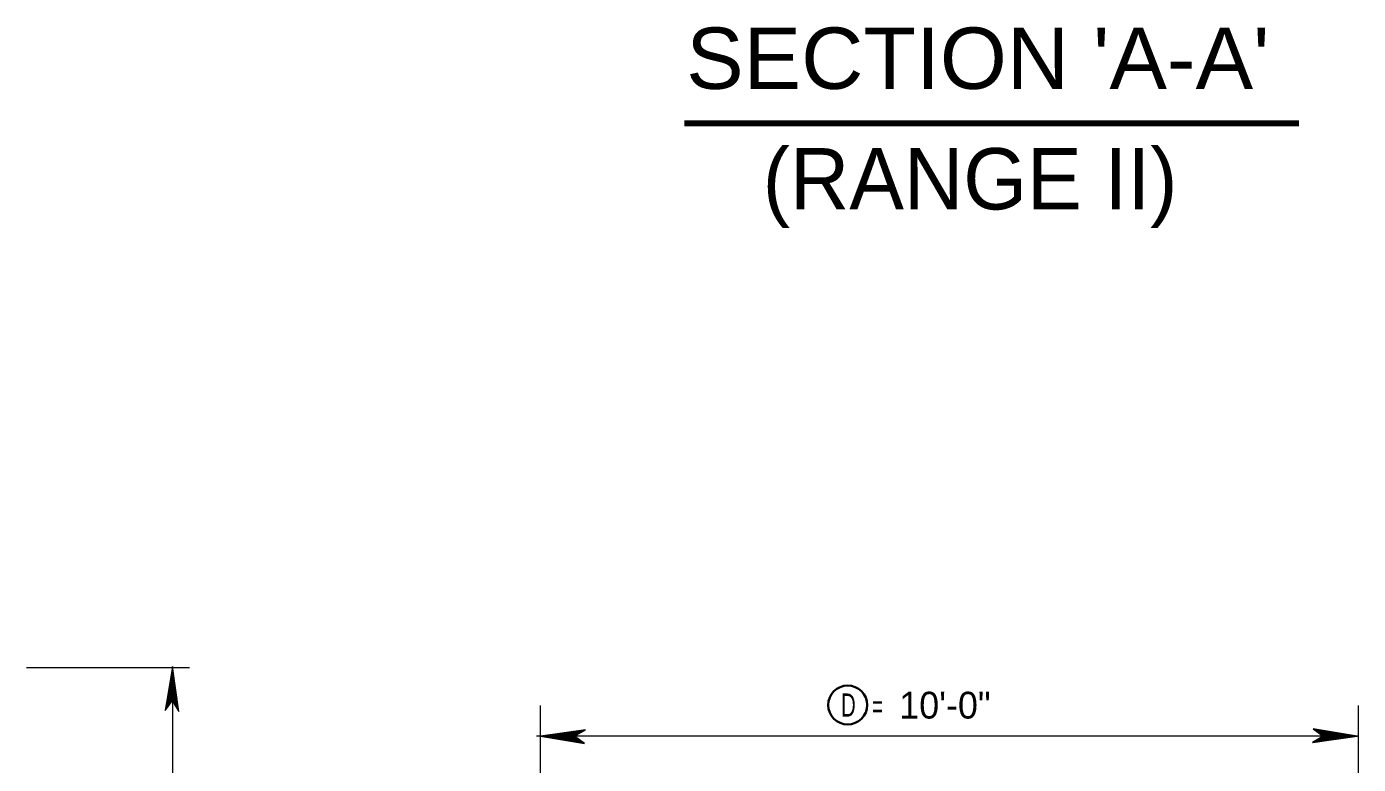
# Model space of a CAD drawing. Extents: x 144 to 252, y 360 to 425.
# Drawn here: x 182.53 to 198.81, y 378.68 to 387.71 of the extents above; entities that cross this region are included whole.
import ezdxf
from ezdxf.enums import TextEntityAlignment as Align

# ---------------------------------------------------------------- set-up
doc = ezdxf.new("R2010")
doc.units = 0
doc.header["$LTSCALE"] = 0.13
for name, color, linetype, lineweight in [('1', 7, 'Continuous', 40), ('14', 7, 'Continuous', 13), ('16', 7, 'Continuous', 13), ('3', 7, 'Continuous', 13)]:
    doc.layers.add(name, color=color, linetype=linetype, lineweight=lineweight)

msp = doc.modelspace()

# ---------------------------------------------------------------- linework, layer by layer
at = {"layer": '1', "lineweight": 13}
for p, q in [((184.5221, 379.866), (182.5307, 379.866)), ((184.3167, 377.2068), (184.3167, 379.8775))]:
    msp.add_line(p, q, dxfattribs=at)
at = {"layer": '1', "lineweight": 35}
msp.add_circle((192.5684, 379.409), 0.238, dxfattribs=at)
at = {"layer": '14', "lineweight": 106}
msp.add_line((190.5739, 386.5247), (198.0812, 386.5247), dxfattribs=at)
at = {"layer": '3'}
for p, q in [((184.3126, 379.8803), (184.2233, 379.3427)), ((184.3119, 379.8659), (184.2257, 379.3459)), ((184.3119, 379.8551), (184.228, 379.3492)), ((184.3119, 379.8407), (184.2312, 379.3534)), ((184.3119, 379.8279), (184.2338, 379.3572)), ((184.3119, 379.8166), (184.2362, 379.3605)), ((184.3868, 379.3376), (184.3119, 379.8659)), ((184.3848, 379.3411), (184.3119, 379.8551)), ((184.3822, 379.3457), (184.3119, 379.8407)), ((184.3798, 379.3497), (184.3119, 379.8279)), ((184.3798, 379.3497), (184.3119, 379.8279)), ((184.3776, 379.3534), (184.3119, 379.8166)), ((184.3126, 379.4649), (184.3126, 379.8803)), ((184.3903, 379.3316), (184.3126, 379.8803)), ((184.3119, 379.8022), (184.2394, 379.3648)), ((184.3119, 379.7894), (184.2422, 379.3685)), ((184.3119, 379.7757), (184.2451, 379.3726)), ((184.3119, 379.7618), (184.2481, 379.3767)), ((184.3119, 379.7486), (184.2509, 379.3806)), ((184.3119, 379.7347), (184.2539, 379.3847)), ((184.3119, 379.7221), (184.2566, 379.3884)), ((184.3119, 379.7107), (184.2591, 379.3918)), ((184.3119, 379.695), (184.2624, 379.3964)), ((184.3119, 379.6812), (184.2654, 379.4005)), ((184.3114, 379.6632), (184.2685, 379.4047)), ((184.3481, 379.404), (184.3114, 379.6632)), ((184.3749, 379.358), (184.3119, 379.8022)), ((184.3725, 379.3621), (184.3119, 379.7894)), ((184.37, 379.3665), (184.3119, 379.7757)), ((184.3674, 379.3709), (184.3119, 379.7618)), ((184.3649, 379.3752), (184.3119, 379.7486)), ((184.3622, 379.3797), (184.3119, 379.7347)), ((184.36, 379.3837), (184.3119, 379.7221)), ((184.3577, 379.3874), (184.3119, 379.7107)), ((184.3549, 379.3924), (184.3119, 379.695)), ((184.3522, 379.3968), (184.3119, 379.6812)), ((184.35, 379.4008), (184.313, 379.6616)), ((184.3114, 379.6492), (184.2715, 379.4089)), ((184.3114, 379.6361), (184.2743, 379.4127)), ((184.3119, 379.627), (184.2771, 379.4165)), ((184.3119, 379.615), (184.2797, 379.4201)), ((184.3119, 379.6012), (184.2827, 379.4242)), ((184.3119, 379.5855), (184.2859, 379.4288)), ((184.3119, 379.5729), (184.2887, 379.4325)), ((184.3119, 379.5597), (184.2915, 379.4364)), ((184.3119, 379.5477), (184.2942, 379.44)), ((184.3119, 379.5332), (184.2972, 379.4443)), ((184.3119, 379.5193), (184.3002, 379.4484)), ((184.3119, 379.5067), (184.3029, 379.4521)), ((184.3119, 379.4934), (184.3057, 379.456)), ((184.3455, 379.4084), (184.3114, 379.6492)), ((184.343, 379.4127), (184.3114, 379.6361)), ((184.3422, 379.4142), (184.3119, 379.627)), ((184.3399, 379.4181), (184.3119, 379.615)), ((184.3372, 379.4225), (184.3119, 379.6012)), ((184.3344, 379.4275), (184.3119, 379.5855)), ((184.332, 379.4316), (184.3119, 379.5729)), ((184.3295, 379.4358), (184.3119, 379.5597)), ((184.3272, 379.4397), (184.3119, 379.5477)), ((184.3246, 379.4443), (184.3119, 379.5332)), ((184.322, 379.4487), (184.3119, 379.5193)), ((184.3197, 379.4528), (184.3119, 379.5067)), ((184.2233, 379.3427), (184.3124, 379.4652)), ((184.3119, 379.482), (184.3082, 379.4594)), ((184.3119, 379.4718), (184.3104, 379.4624)), ((184.315, 379.4607), (184.3119, 379.482)), ((184.3124, 379.4652), (184.3903, 379.3316)), ((184.3166, 379.4581), (184.313, 379.4832)), ((188.8108, 376.1394), (188.8108, 379.4017)), ((198.8108, 375.9887), (198.8108, 379.4017)), ((188.8108, 379.0267), (188.7653, 379.0267)), ((189.3618, 379.106), (188.813, 379.0283)), ((188.813, 379.0283), (189.3507, 378.939)), ((189.2284, 379.0283), (188.813, 379.0283)), ((194.8025, 379.0267), (188.8198, 379.0267)), ((189.3558, 379.1025), (188.8274, 379.0276)), ((188.8274, 379.0276), (189.3474, 378.9413)), ((189.3522, 379.1005), (188.8382, 379.0276)), ((188.8382, 379.0276), (189.3442, 378.9437)), ((189.3477, 379.0978), (188.8527, 379.0276)), ((188.8527, 379.0276), (189.3399, 378.9468)), ((189.3436, 379.0954), (188.8654, 379.0276)), ((189.3436, 379.0954), (188.8654, 379.0276)), ((188.8654, 379.0276), (189.3362, 378.9495)), ((189.3399, 379.0933), (188.8767, 379.0276)), ((188.8767, 379.0276), (189.3328, 378.9519)), ((189.3353, 379.0906), (188.8912, 379.0276)), ((188.8912, 379.0276), (189.3286, 378.9551)), ((189.3312, 379.0882), (188.9039, 379.0276)), ((188.9039, 379.0276), (189.3248, 378.9578)), ((189.3268, 379.0857), (188.9177, 379.0276)), ((188.9177, 379.0276), (189.3208, 378.9607)), ((189.3224, 379.0831), (188.9315, 379.0276)), ((188.9315, 379.0276), (189.3167, 378.9638)), ((189.3182, 379.0806), (188.9447, 379.0276)), ((188.9447, 379.0276), (189.3127, 378.9666)), ((189.3137, 379.0779), (188.9587, 379.0276)), ((188.9587, 379.0276), (189.3087, 378.9696)), ((189.3097, 379.0757), (188.9712, 379.0276)), ((188.9712, 379.0276), (189.3049, 378.9722)), ((189.3059, 379.0734), (188.9827, 379.0276)), ((188.9827, 379.0276), (189.3015, 378.9747)), ((189.3009, 379.0706), (188.9983, 379.0276)), ((188.9983, 379.0276), (189.2969, 378.9781)), ((189.2965, 379.0679), (189.0122, 379.0276)), ((189.0122, 379.0276), (189.2928, 378.9811)), ((189.2893, 379.0637), (189.0302, 379.0271)), ((189.0302, 379.0271), (189.2886, 378.9842)), ((189.2925, 379.0657), (189.0317, 379.0287)), ((189.2849, 379.0612), (189.0441, 379.0271)), ((189.0441, 379.0271), (189.2844, 378.9872)), ((189.2807, 379.0587), (189.0572, 379.0271)), ((189.0572, 379.0271), (189.2806, 378.99)), ((189.2792, 379.0578), (189.0663, 379.0276)), ((189.0663, 379.0276), (189.2768, 378.9928)), ((189.2752, 379.0556), (189.0783, 379.0276)), ((189.0783, 379.0276), (189.2732, 378.9953)), ((189.2708, 379.0529), (189.0922, 379.0276)), ((189.0922, 379.0276), (189.2692, 378.9983)), ((189.2658, 379.0501), (189.1078, 379.0276)), ((189.1078, 379.0276), (189.2645, 379.0016)), ((189.2618, 379.0477), (189.1204, 379.0276)), ((189.1204, 379.0276), (189.2608, 379.0043)), ((189.2575, 379.0452), (189.1337, 379.0276)), ((189.1337, 379.0276), (189.2569, 379.0072)), ((189.2537, 379.0429), (189.1457, 379.0276)), ((189.1457, 379.0276), (189.2533, 379.0098)), ((189.249, 379.0403), (189.1602, 379.0276)), ((189.1602, 379.0276), (189.2491, 379.0128)), ((189.2446, 379.0377), (189.174, 379.0276)), ((189.174, 379.0276), (189.2449, 379.0158)), ((189.2405, 379.0353), (189.1867, 379.0276)), ((189.1867, 379.0276), (189.2412, 379.0186)), ((189.1999, 379.0276), (189.2373, 379.0214)), ((189.2353, 379.0322), (189.2102, 379.0287)), ((189.2326, 379.0307), (189.2113, 379.0276)), ((189.2113, 379.0276), (189.2339, 379.0238)), ((189.2215, 379.0276), (189.2309, 379.0261)), ((189.2282, 379.0281), (189.3618, 379.106)), ((189.3507, 378.939), (189.2282, 379.0281)), ((196.8025, 379.0267), (190.8198, 379.0267)), ((196.8025, 379.0267), (190.8198, 379.0267)), ((198.8025, 379.0267), (192.8198, 379.0267)), ((198.3825, 379.0269), (198.2489, 378.949)), ((198.2489, 378.949), (198.7977, 379.0267)), ((198.2549, 378.9525), (198.7832, 379.0274)), ((198.2584, 378.9545), (198.7724, 379.0274)), ((198.7977, 379.0267), (198.26, 379.116)), ((198.26, 379.116), (198.3825, 379.0269)), ((198.263, 378.9572), (198.758, 379.0274)), ((198.7832, 379.0274), (198.2632, 379.1137)), ((198.7724, 379.0274), (198.2665, 379.1113)), ((198.2671, 378.9596), (198.7452, 379.0274)), ((198.2671, 378.9596), (198.7452, 379.0274)), ((198.758, 379.0274), (198.2707, 379.1082)), ((198.2707, 378.9617), (198.7339, 379.0274)), ((198.7452, 379.0274), (198.2745, 379.1055)), ((198.2753, 378.9644), (198.7195, 379.0274)), ((198.7339, 379.0274), (198.2778, 379.1031)), ((198.2794, 378.9668), (198.7067, 379.0274)), ((198.7195, 379.0274), (198.2821, 379.0999)), ((198.2838, 378.9693), (198.693, 379.0274)), ((198.7067, 379.0274), (198.2858, 379.0972)), ((198.2883, 378.9719), (198.6792, 379.0274)), ((198.693, 379.0274), (198.2899, 379.0942)), ((198.2925, 378.9744), (198.6659, 379.0274)), ((198.6792, 379.0274), (198.294, 379.0913)), ((198.297, 378.9771), (198.652, 379.0274)), ((198.6659, 379.0274), (198.2979, 379.0884)), ((198.301, 378.9793), (198.6394, 379.0274)), ((198.652, 379.0274), (198.302, 379.0854)), ((198.3047, 378.9816), (198.628, 379.0274)), ((198.6394, 379.0274), (198.3057, 379.0827)), ((198.628, 379.0274), (198.3092, 379.0802)), ((198.3097, 378.9844), (198.6123, 379.0274)), ((198.6123, 379.0274), (198.3137, 379.0769)), ((198.3142, 378.9871), (198.5985, 379.0274)), ((198.5985, 379.0274), (198.3178, 379.0739)), ((198.3182, 378.9893), (198.5789, 379.0263)), ((198.3213, 378.9912), (198.5805, 379.0279)), ((198.5805, 379.0279), (198.3221, 379.0708)), ((198.3257, 378.9938), (198.5666, 379.0279)), ((198.5666, 379.0279), (198.3262, 379.0678)), ((198.33, 378.9963), (198.5534, 379.0279)), ((198.5534, 379.0279), (198.3301, 379.065)), ((198.3315, 378.9972), (198.5443, 379.0274)), ((198.5443, 379.0274), (198.3338, 379.0623)), ((198.3354, 378.9994), (198.5323, 379.0274)), ((198.5323, 379.0274), (198.3374, 379.0597)), ((198.3398, 379.0021), (198.5185, 379.0274)), ((198.5185, 379.0274), (198.3415, 379.0567)), ((198.3448, 379.0049), (198.5028, 379.0274)), ((198.5028, 379.0274), (198.3462, 379.0534)), ((198.3489, 379.0073), (198.4903, 379.0274)), ((198.4903, 379.0274), (198.3498, 379.0507)), ((198.3532, 379.0098), (198.477, 379.0274)), ((198.477, 379.0274), (198.3537, 379.0478)), ((198.357, 379.0121), (198.465, 379.0274)), ((198.465, 379.0274), (198.3573, 379.0452)), ((198.4505, 379.0274), (198.3616, 379.0422)), ((198.3617, 379.0147), (198.4505, 379.0274)), ((198.4367, 379.0274), (198.3657, 379.0392)), ((198.3661, 379.0173), (198.4367, 379.0274)), ((198.424, 379.0274), (198.3694, 379.0364)), ((198.3702, 379.0197), (198.424, 379.0274)), ((198.4108, 379.0274), (198.3733, 379.0336)), ((198.3754, 379.0227), (198.4005, 379.0263)), ((198.3993, 379.0274), (198.3767, 379.0312)), ((198.3781, 379.0243), (198.3993, 379.0274)), ((198.3892, 379.0274), (198.3798, 379.0289)), ((198.3822, 379.0267), (198.7977, 379.0267))]:
    msp.add_line(p, q, dxfattribs=at)

# ---------------------------------------------------------------- texts
at = {"layer": '1'}
for s, width, p in [('D', 0.65, (192.5772, 379.2671)), ('=', 0.6, (192.9339, 379.2517))]:
    msp.add_text(s, height=0.2833, dxfattribs=dict(at, width=width)).set_placement(p, align=Align.CENTER)
at = {"layer": '16', "width": 1.05}
msp.add_text("SECTION 'A-A'", height=0.75, dxfattribs=at).set_placement((194.1592, 386.9446), align=Align.CENTER)
at = {"layer": '16'}
for s, height, p in [('(RANGE II)', 0.75, (194.0644, 385.4699)), ('10\'-0"', 0.3281, (193.757, 379.2435))]:
    msp.add_text(s, height=height, dxfattribs=at).set_placement(p, align=Align.CENTER)

doc.saveas('drawing.dxf')
